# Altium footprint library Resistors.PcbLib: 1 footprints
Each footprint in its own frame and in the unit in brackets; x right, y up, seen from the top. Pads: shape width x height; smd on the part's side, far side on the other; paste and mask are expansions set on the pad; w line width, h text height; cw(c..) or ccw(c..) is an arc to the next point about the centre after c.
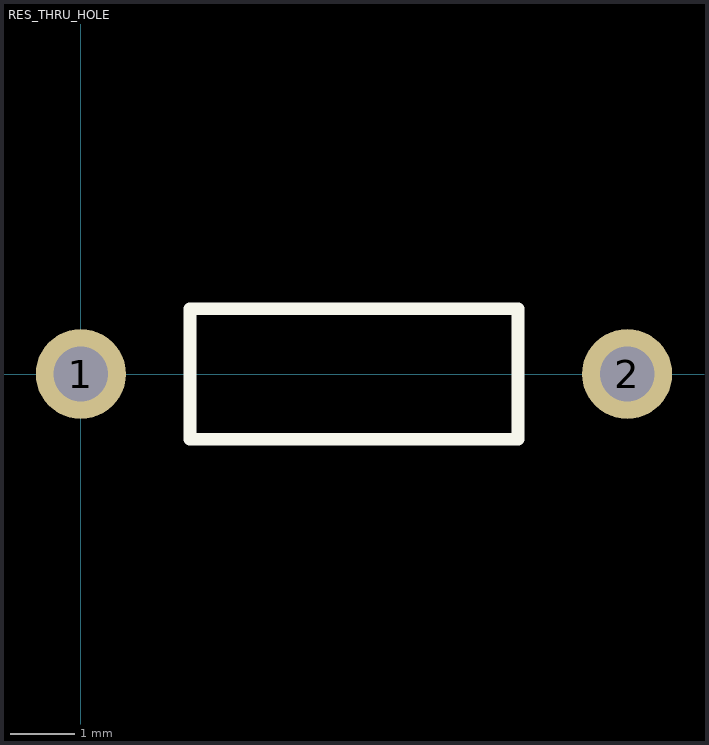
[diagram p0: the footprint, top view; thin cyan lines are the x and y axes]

## RES_THRU_HOLE [mm]
pads (2):
  round 1.4 hole 0.85: 1(0,0) 2(8.5,0)
Top Overlay:
  lines w0.2: 1.7,-1.016 6.8,-1.016 6.8,1.016 1.7,1.016 1.7,-1.016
